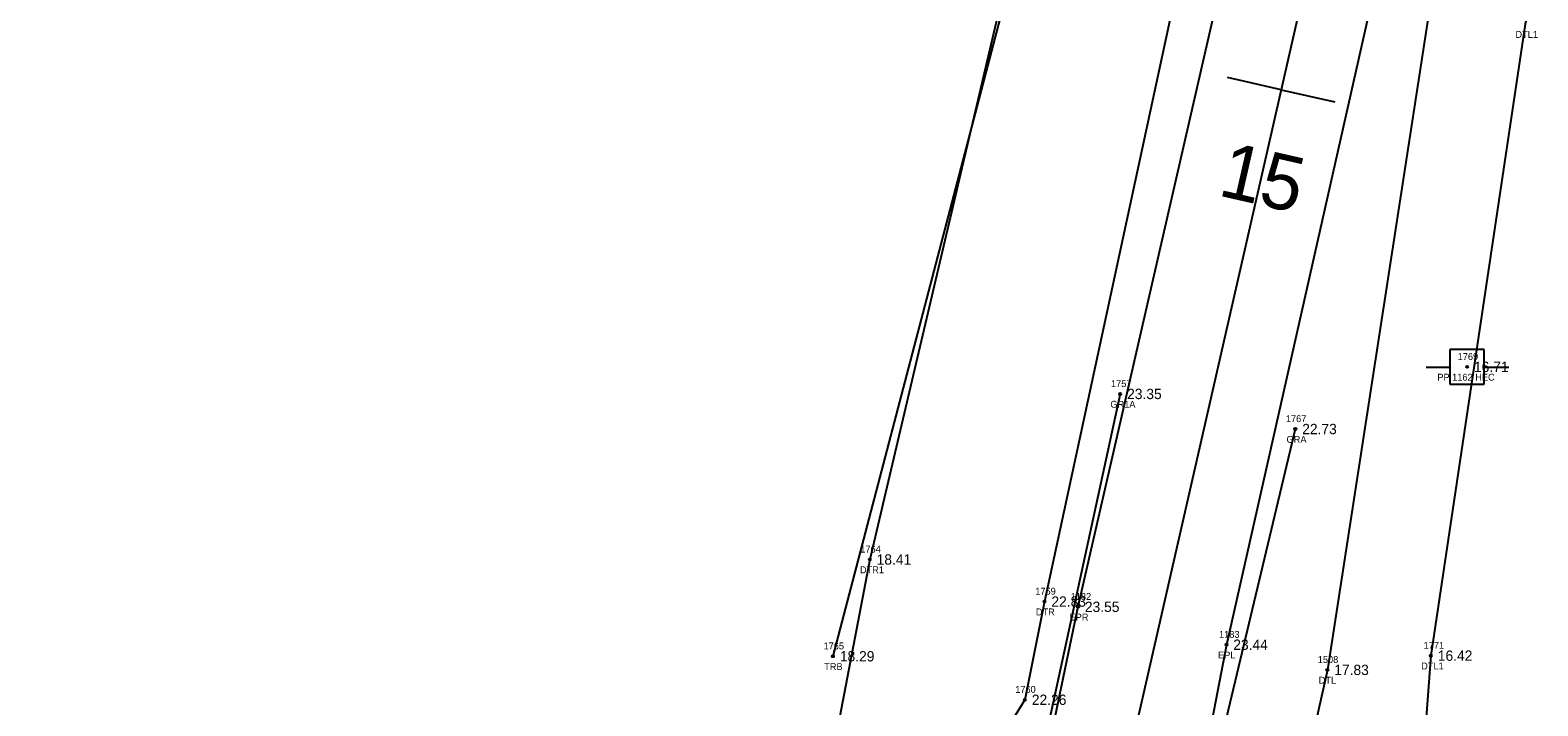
# Model space of a CAD drawing. Extents: x 2654414 to 2656963, y 761776 to 764965.
# Drawn here: x 2655563.1 to 2655781.9, y 763282.4 to 763380.5 of the extents above; entities that cross this region are included whole.
import ezdxf

# ---------------------------------------------------------------- set-up
doc = ezdxf.new("R2010")
doc.units = 0
for name, color, linetype in [('Default', 7, 'Continuous'), ('RD_EX_GuardRail', 7, 'Continuous'), ('RD_EX_GuardRail_txCode', 7, 'Continuous'), ('RD_EX_H2O', 7, 'Continuous'), ('RD_EX_H2O_txCode', 7, 'Continuous'), ('RD_EX_Road', 7, 'Continuous'), ('RD_EX_Road_txCode', 7, 'Continuous'), ('RD_EX_TX_GuardRail_ELEV', 7, 'Continuous'), ('RD_EX_TX_H2O_ELEV', 7, 'Continuous'), ('RD_EX_TX_Road_ELEV', 7, 'Continuous'), ('RD_EX_TX_VEG_ELEV', 7, 'Continuous'), ('RD_EX_UT', 7, 'Continuous'), ('RD_EX_UT_txCode', 7, 'Continuous'), ('RD_EX_VEG', 7, 'Continuous'), ('RD_EX_VEG_txCode', 7, 'Continuous'), ('RD_HC_Cl', 7, 'Continuous'), ('RD_HC_Data_Tic', 7, 'Continuous'), ('RD_HC_Survey_ELEV', 7, 'Continuous'), ('RD_HC_TX_Sta50', 7, 'Continuous'), ('RD_SMD_Locator', 7, 'Continuous')]:
    doc.layers.add(name, color=color, linetype=linetype)

msp = doc.modelspace()

# ---------------------------------------------------------------- linework, layer by layer
at = {"layer": 'Default'}
msp.add_line((2656050.51, 764712.37), (2655383.26, 761787.51), dxfattribs=at)
at = {"layer": 'RD_EX_GuardRail'}
for points in [[(2655721.32, 763327.66), (2655710.81, 763279.37), (2655699.76, 763230.75), (2655688.36, 763182.86)], [(2655746.73, 763322.57), (2655735.51, 763275.5), (2655724.18, 763225.54)]]:
    msp.add_lwpolyline(points, dxfattribs=at)
at = {"layer": 'RD_EX_H2O'}
for points in [[(2655866.2, 763781.92), (2655858.43, 763782.12), (2655853.29, 763757.63), (2655831.21, 763662.14), (2655807.21, 763570.59), (2655787.76, 763479.91), (2655766.41, 763384.86), (2655751.38, 763287.62), (2655745.55, 763261.6)], [(2655866.2, 763781.92), (2655866.81, 763773.88), (2655862.68, 763756.12), (2655841.51, 763659.39), (2655821.68, 763567.67), (2655800.98, 763476.96), (2655780.09, 763381.34), (2655766.41, 763289.68), (2655763.83, 763255.61)], [(2655761.66, 763536.79), (2655753.68, 763542.9), (2655743.24, 763538.2), (2655729.93, 763492.02), (2655706.75, 763396.29), (2655684.97, 763303.64), (2655679.52, 763275.1)], [(2655761.66, 763536.79), (2655754.62, 763487.9), (2655730.78, 763392.48), (2655710.33, 763297.53), (2655707.49, 763283.28), (2655700.44, 763271.88)]]:
    msp.add_lwpolyline(points, dxfattribs=at)
at = {"layer": 'RD_EX_Road'}
for points in [[(2656041.72, 764723.31), (2656018.5, 764622.03), (2656002.75, 764552.49), (2655997.43, 764530.02), (2655974.74, 764429.64), (2655952.97, 764333.57), (2655930.52, 764235.7), (2655909.18, 764142.93), (2655887.93, 764050.57), (2655866.91, 763957.26), (2655846.82, 763869.53), (2655845.21, 763862.22), (2655839.99, 763839.71), (2655823.38, 763766.66), (2655801.33, 763669.93), (2655780.03, 763576.53), (2655774.26, 763551.85), (2655771.37, 763539.86), (2655759.09, 763486.9), (2655736.94, 763391.72), (2655715.19, 763296.77), (2655711.35, 763278.45)], [(2655852.89, 763796.34), (2655850.73, 763786.52), (2655844.88, 763760.97), (2655822.62, 763664.7), (2655801.12, 763571.82), (2655780.32, 763481.64), (2655758.16, 763386.38), (2655736.73, 763291.27), (2655733.33, 763273.46)]]:
    msp.add_lwpolyline(points, dxfattribs=at)
at = {"layer": 'RD_EX_UT'}
for p, q in [((2655774.15, 763334.1), (2655769.15, 763334.1)), ((2655769.15, 763334.1), (2655769.15, 763329.1)), ((2655774.15, 763329.1), (2655774.15, 763334.1)), ((2655765.72, 763331.54), (2655769.19, 763331.54)), ((2655774.08, 763331.54), (2655777.72, 763331.54)), ((2655769.15, 763329.1), (2655774.15, 763329.1))]:
    msp.add_line(p, q, dxfattribs=at)
at = {"layer": 'RD_EX_VEG'}
msp.add_line((2655745.4, 763540.55), (2655679.63, 763289.59), dxfattribs=at)
at = {"layer": 'RD_HC_Cl'}
msp.add_line((2656050.51, 764712.37), (2655383.26, 761787.51), dxfattribs=at)
at = {"layer": 'RD_HC_Data_Tic'}
for q in [(2655736.89, 763373.59), (2655752.49, 763370.03)]:
    msp.add_line((2655744.69, 763371.81), q, dxfattribs=at)
at = {"layer": 'RD_SMD_Locator'}
for centre in [(2655771.66, 763331.59), (2655721.32, 763327.66), (2655746.73, 763322.57), (2655684.97, 763303.64), (2655710.33, 763297.53), (2655715.19, 763296.77), (2655736.73, 763291.27), (2655679.63, 763289.59), (2655766.41, 763289.68), (2655751.38, 763287.62), (2655707.49, 763283.28)]:
    msp.add_circle(centre, 0.15, dxfattribs=at)

# ---------------------------------------------------------------- texts
at = {"layer": 'RD_EX_GuardRail_txCode'}
for s, p in [('1757', (2655719.98, 763328.66)), ('GR1A', (2655719.89, 763325.66)), ('1767', (2655745.36, 763323.57)), ('GRA', (2655745.46, 763320.57))]:
    msp.add_text(s, height=1, dxfattribs=at).set_placement(p)
at = {"layer": 'RD_EX_H2O_txCode'}
for s, p in [('DTL1', (2655778.68, 763379.34)), ('1764', (2655683.6, 763304.64)), ('DTR1', (2655683.54, 763301.64)), ('1759', (2655708.99, 763298.53)), ('DTR', (2655709.07, 763295.53)), ('1771', (2655765.35, 763290.68)), ('1508', (2655749.99, 763288.62)), ('DTL1', (2655765, 763287.68)), ('DTL', (2655750.13, 763285.62)), ('1760', (2655706.08, 763284.28))]:
    msp.add_text(s, height=1, dxfattribs=at).set_placement(p)
at = {"layer": 'RD_EX_Road_txCode'}
for s, p in [('1182', (2655714.13, 763297.77)), ('EPR', (2655713.96, 763294.77)), ('1183', (2655735.66, 763292.27)), ('EPL', (2655735.52, 763289.27))]:
    msp.add_text(s, height=1, dxfattribs=at).set_placement(p)
at = {"layer": 'RD_EX_TX_GuardRail_ELEV'}
for s, p in [('23.35', (2655722.32, 763326.91)), ('22.73', (2655747.73, 763321.82))]:
    msp.add_text(s, height=1.5, dxfattribs=at).set_placement(p)
at = {"layer": 'RD_EX_TX_H2O_ELEV'}
for s, p in [('18.41', (2655685.97, 763302.89)), ('22.83', (2655711.33, 763296.78)), ('16.42', (2655767.41, 763288.93)), ('17.83', (2655752.38, 763286.87)), ('22.26', (2655708.49, 763282.53))]:
    msp.add_text(s, height=1.5, dxfattribs=at).set_placement(p)
at = {"layer": 'RD_EX_TX_Road_ELEV'}
for s, p in [('23.55', (2655716.19, 763296.02)), ('23.44', (2655737.73, 763290.52))]:
    msp.add_text(s, height=1.5, dxfattribs=at).set_placement(p)
at = {"layer": 'RD_EX_TX_VEG_ELEV'}
msp.add_text('18.29', height=1.5, dxfattribs=at).set_placement((2655680.63, 763288.84))
at = {"layer": 'RD_EX_UT_txCode'}
for s, p in [('1769', (2655770.29, 763332.59)), ('PP 1162 HEC', (2655767.34, 763329.59))]:
    msp.add_text(s, height=1, dxfattribs=at).set_placement(p)
at = {"layer": 'RD_EX_VEG_txCode'}
for s, p in [('1765', (2655678.26, 763290.59)), ('TRB', (2655678.36, 763287.59))]:
    msp.add_text(s, height=1, dxfattribs=at).set_placement(p)
at = {"layer": 'RD_HC_Survey_ELEV'}
msp.add_text('16.71', height=1.5, dxfattribs=at).set_placement((2655772.66, 763330.84))
at = {"layer": 'RD_HC_TX_Sta50'}
msp.add_text('15', height=8, rotation=347.1349, dxfattribs=at).set_placement((2655735.33, 763356.51))

doc.saveas('drawing.dxf')
